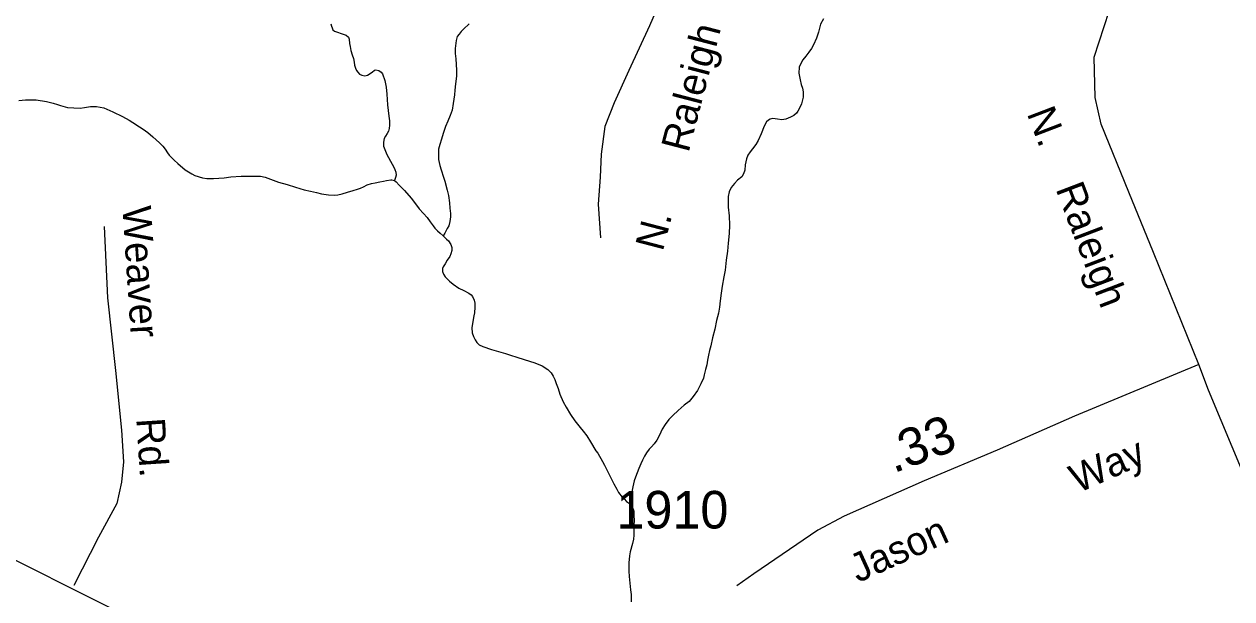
# Model space of a CAD drawing. Extents: x 2126262 to 2293712, y 749403 to 919119.
# Drawn here: x 2137114 to 2141122, y 839596 to 841505 of the extents above; entities that cross this region are included whole.
import ezdxf

# ---------------------------------------------------------------- set-up
doc = ezdxf.new("R2010")
doc.units = 0
for name, color, linetype in [('Exist Hydrographic Misc Water Feature', 7, 'Continuous'), ('Exist Road Non-System Type 51', 7, 'Continuous'), ('Exist Road Non-System Type 51 Label', 7, 'Continuous'), ('Exist Road Secondary Mileage Hundredths English Label', 7, 'Continuous'), ('Exist Road Secondary Type 51 Attributed', 7, 'Continuous'), ('Exist Road Secondary Type 51 Label', 7, 'Continuous'), ('Exist Road Secondary Type 51 Number Label', 7, 'Continuous')]:
    doc.layers.add(name, color=color, linetype=linetype)

msp = doc.modelspace()

# ---------------------------------------------------------------- linework, layer by layer
at = {"layer": 'Exist Hydrographic Misc Water Feature'}
for points in [[(2138131.8, 841506), (2138133.8, 841497.6), (2138135.9, 841492), (2138138.6, 841485.5), (2138143.9, 841481.9), (2138153.5, 841478.4), (2138166, 841474.1), (2138182, 841468), (2138189.8, 841461.5), (2138192.1, 841454.7)], [(2138591.1, 841506.3), (2138571.6, 841488.1), (2138563.8, 841480), (2138557.9, 841472), (2138551.3, 841463.6), (2138547.8, 841449.9), (2138544.4, 841423.7), (2138544.2, 841407.5), (2138546.6, 841389.2), (2138548.9, 841351.6), (2138548.9, 841331.7), (2138545.2, 841307.1), (2138543.3, 841285.9)], [(2139767.1, 841522.2), (2139756.8, 841504.7), (2139749.7, 841478.6), (2139743.7, 841458), (2139733.7, 841436), (2139727.3, 841423.9), (2139717.7, 841411.6), (2139708.2, 841398.1), (2139698, 841385.8), (2139690.6, 841371.5)], [(2138192.1, 841454.7), (2138193.9, 841440.6), (2138196.2, 841430.9), (2138198.4, 841416.8), (2138202.5, 841402.8), (2138206.4, 841390.4), (2138208.7, 841378.7), (2138210.7, 841368.3), (2138213, 841358.2), (2138216.9, 841350.7), (2138221, 841345.2), (2138227.1, 841338.2), (2138234.9, 841335), (2138245, 841333.1), (2138253, 841335.5), (2138269, 841344.8), (2138276.8, 841351.4), (2138280.9, 841352.8), (2138290.7, 841350.9), (2138298.7, 841345.2), (2138302.8, 841339.3), (2138311.2, 841317.8), (2138315.1, 841295.7), (2138317.6, 841271.8), (2138319.8, 841237.3), (2138322.1, 841217.5), (2138324.1, 841199.4), (2138326.2, 841183.6), (2138326.4, 841169.8), (2138325, 841158.2), (2138322.7, 841149.3), (2138318.8, 841141.3), (2138312.9, 841133.3), (2138308.3, 841125.1), (2138306.7, 841112.7), (2138306.7, 841099.8), (2138312.9, 841083), (2138317.4, 841071.4), (2138323.3, 841061.6), (2138329.5, 841050.1), (2138335.4, 841040.2), (2138339.7, 841031.9), (2138343.6, 841022), (2138347.1, 841012.9), (2138348.1, 841003.8), (2138345.9, 840995.6), (2138342.6, 840985.6)], [(2139690.6, 841371.5), (2139686.3, 841361.6), (2139684.9, 841341.9), (2139688.8, 841319.8), (2139692.9, 841304.2), (2139696.8, 841291.8), (2139699.2, 841280.2), (2139699.2, 841262.3), (2139693.3, 841240), (2139689.4, 841229.7), (2139681.6, 841215.8), (2139677.5, 841209.2), (2139667.8, 841201.3), (2139657.4, 841195.6), (2139642, 841189.4), (2139628.1, 841187.4), (2139613.9, 841189.2), (2139598.1, 841191.2), (2139589.9, 841188.7), (2139583.8, 841186.4), (2139577.6, 841180.9), (2139569.6, 841166.2), (2139559.6, 841141), (2139549.9, 841118.5), (2139542.3, 841104.6), (2139530.7, 841090.2), (2139522.7, 841080.4), (2139515.1, 841069.8), (2139510.8, 841057.5), (2139507.1, 841038.1), (2139505.4, 841020.1), (2139501.3, 841007.8), (2139495.4, 840998.2), (2139481.4, 840986.1), (2139471.6, 840975.8), (2139460.1, 840962.1), (2139453.6, 840948.1), (2139450.1, 840932.8), (2139450.1, 840915.3), (2139450.1, 840897.5), (2139453.8, 840868.5), (2139454.6, 840837.5), (2139453.4, 840809.4), (2139449.7, 840777.5), (2139448, 840751.3), (2139443.7, 840721.1), (2139440.2, 840687.6), (2139436.1, 840665.5), (2139430.6, 840635.1), (2139426.9, 840611.7), (2139423.2, 840585.5), (2139421.6, 840565), (2139417.9, 840545.3), (2139411.7, 840520.7), (2139406, 840491.5), (2139398.2, 840462.7), (2139392.7, 840436.8), (2139388.8, 840421.1), (2139384.7, 840405.1), (2139381.6, 840388.5), (2139378.9, 840373.1), (2139374.8, 840358.3), (2139371.1, 840340.6), (2139367.9, 840328.9), (2139359.6, 840310.3), (2139348, 840288.5), (2139334, 840268.3), (2139320.3, 840252.1), (2139304.1, 840240), (2139284.4, 840221.4), (2139266.6, 840205.5), (2139252.8, 840191.7), (2139240.7, 840175.7), (2139230.9, 840159.4), (2139227.2, 840149.8), (2139221.2, 840137.7), (2139213.2, 840123.1), (2139205.2, 840110.9), (2139195.6, 840101.4), (2139187.6, 840093.3), (2139179.6, 840081.1), (2139172.6, 840070.4), (2139165.7, 840056.8), (2139160.3, 840044.7), (2139154.2, 840029), (2139148, 840014.5), (2139142.3, 840000.7), (2139138.6, 839988.3), (2139133.7, 839968.8), (2139130, 839951.5), (2139127.1, 839934.5), (2139125.1, 839924.7), (2139123, 839912.4)], [(2137096.3, 841250.9), (2137118.2, 841252.9), (2137132.4, 841253.6), (2137153.9, 841253.1), (2137188.4, 841247.5), (2137209.9, 841242.3), (2137224, 841237.7), (2137234.1, 841234.1), (2137258.1, 841228.1), (2137278.4, 841226.6), (2137300.3, 841226.1), (2137314.3, 841228.5), (2137334.3, 841231.1), (2137354.2, 841230.9), (2137378.8, 841226.4), (2137408.2, 841213.5), (2137440.6, 841198), (2137462.7, 841186.1), (2137474.6, 841178.2), (2137496.5, 841164), (2137508.8, 841156.5), (2137524.6, 841144.7), (2137540.6, 841130.9), (2137563.2, 841110.9), (2137573.6, 841099.1), (2137581.4, 841089.5), (2137589.4, 841076.9), (2137595.4, 841069.5), (2137611.4, 841053.3), (2137623.9, 841041.6), (2137647.9, 841021.4), (2137670.2, 841007.8), (2137680.3, 841001.8), (2137706.1, 840993.9), (2137720.3, 840992.2), (2137742, 840992.5), (2137778.1, 840994.8), (2137799.8, 840997.2), (2137834.1, 840999.7), (2137866, 840999.7)], [(2138543.3, 841285.9), (2138541.5, 841269.5), (2138539.6, 841255.6), (2138537.8, 841241.7), (2138534.1, 841219.5), (2138528.2, 841201.8), (2138520.4, 841183.1), (2138512.4, 841165.2), (2138504.6, 841141.6), (2138498.8, 841122.6), (2138492.9, 841104.8), (2138489, 841089.6), (2138489.2, 841072.9), (2138489.2, 841055.1), (2138493.7, 841035.4), (2138497.6, 841021.4), (2138506, 840997), (2138509.9, 840983), (2138518.1, 840953.4), (2138522.4, 840935.3), (2138524.9, 840911.4), (2138526.9, 840893.2), (2138528.6, 840875.5), (2138529, 840865.3), (2138527.1, 840848.9), (2138523.7, 840835.2), (2138517.3, 840825.7), (2138509.9, 840811), (2138504.6, 840802)], [(2137866, 840999.7), (2137886.1, 841000.3), (2137897.8, 840999.7), (2137913.8, 840996.1), (2137940.3, 840986.1), (2137957.9, 840980.5), (2137986.4, 840972.6), (2138014.7, 840963.8), (2138043.4, 840955), (2138063.7, 840949.9), (2138083.8, 840945.3), (2138100.2, 840941.6), (2138124.2, 840937.9), (2138142.5, 840936.8), (2138154.6, 840938.2), (2138169.3, 840940.8), (2138187.4, 840947), (2138205.8, 840952.3), (2138220, 840956.3), (2138230.4, 840960.4), (2138240.1, 840965), (2138252.6, 840971.2), (2138266.1, 840975.3), (2138278.4, 840977.5), (2138294.2, 840981.1), (2138306.1, 840983.4), (2138316.1, 840985.5), (2138330.3, 840987.9), (2138334, 840987.7), (2138342.6, 840985.6)], [(2138342.6, 840985.6), (2138347.9, 840981.5), (2138358.2, 840969.9), (2138376.4, 840952.1), (2138398.6, 840926.4), (2138412.5, 840908.1), (2138424.8, 840892), (2138439.2, 840876.5), (2138450.9, 840862.9), (2138461.3, 840848.8), (2138471.4, 840834.7), (2138477.3, 840827.2), (2138485.1, 840818.7), (2138494.5, 840811.2), (2138504.6, 840802)], [(2138504.6, 840802), (2138515.9, 840791), (2138521.6, 840785.3), (2138530, 840773.5), (2138533.7, 840763.5), (2138533.3, 840753.1), (2138530.2, 840741.7), (2138526.3, 840733.4), (2138517.9, 840721.3), (2138510.7, 840709), (2138504.4, 840699.4), (2138502.5, 840692.8), (2138502.5, 840683), (2138505, 840674.9), (2138511.1, 840665.5), (2138524.9, 840651.3), (2138537.2, 840641.3), (2138556.7, 840627.8), (2138573.3, 840620), (2138589.3, 840611.5), (2138597.7, 840605.8), (2138601.4, 840599.9), (2138607.3, 840588), (2138609.6, 840578.4), (2138609.4, 840564.6), (2138608.1, 840546.2), (2138605.9, 840535.9), (2138604, 840524.5), (2138600.1, 840495.8), (2138600.5, 840480), (2138604.9, 840467.9), (2138610.6, 840456.2), (2138616.3, 840447.9), (2138624.3, 840440.2), (2138635.8, 840434.5), (2138664.3, 840424.1), (2138710.9, 840410.5), (2138727.9, 840405.5), (2138748.8, 840399.1), (2138773.2, 840391.4), (2138790.8, 840385.8), (2138809.1, 840379.8), (2138832.9, 840370.5), (2138851.9, 840357.5), (2138862.6, 840346.6), (2138869.8, 840336.1), (2138875.3, 840324.4), (2138879.6, 840311.9), (2138885.8, 840294.8), (2138892.1, 840276.4), (2138902.2, 840250.9), (2138912.4, 840232.7), (2138926.6, 840208.2), (2138940.9, 840187), (2138959, 840165.2), (2138969, 840153.5), (2138981.1, 840137.5), (2138993.6, 840117.8), (2139011.5, 840087.9), (2139017.8, 840079.6), (2139033.6, 840052.1), (2139040, 840039.7), (2139062.5, 839995.8), (2139070.7, 839978.3), (2139080.8, 839960.1), (2139086.7, 839949.9), (2139099, 839934.2), (2139104.8, 839928.5), (2139113.2, 839919.9), (2139123, 839912.4)], [(2139123, 839912.4), (2139133.1, 839899.1), (2139137.2, 839887.5), (2139137.2, 839872.9), (2139138, 839856.6), (2139137.6, 839842.4), (2139137.6, 839834.3), (2139137.6, 839824.5), (2139137.4, 839807.9), (2139136.6, 839794.7), (2139132.5, 839780.3), (2139124.9, 839752.6), (2139122.6, 839738.8), (2139121, 839716.3), (2139121, 839688.7), (2139121.4, 839670.4), (2139123.6, 839648.1), (2139125.9, 839626.3), (2139127.9, 839610.6), (2139128.1, 839586.6)]]:
    msp.add_lwpolyline(points, dxfattribs=at)
at = {"layer": 'Exist Road Non-System Type 51'}
msp.add_lwpolyline([(2137379.8, 840832.9), (2137390.8, 840595.8), (2137417.1, 840354.3), (2137436.9, 840156.8), (2137443.5, 840051.4), (2137436.9, 839983.3), (2137421.5, 839913.1), (2137360.1, 839801.1), (2137278.4, 839640.5)], dxfattribs=at)
at = {"layer": 'Exist Road Secondary Type 51 Attributed'}
for points in [[(2139269.1, 841683.8), (2139189.3, 841499.4), (2139120.2, 841350.9), (2139072, 841243.9), (2139040.4, 841164.5), (2139028.5, 841072.8), (2139024.9, 840996.8), (2139019, 840907), (2139026.7, 840794.8)], [(2141011.8, 840374.9), (2140861.7, 840747), (2140779.8, 840946.6), (2140688.5, 841172.5), (2140668.3, 841260.9), (2140665.1, 841395), (2140714.2, 841548)], [(2141011.8, 840374.9), (2140600.1, 840202.7), (2140342.4, 840090.2), (2140100.2, 839988.6), (2139835.3, 839870.5), (2139748.1, 839824.2), (2139535.7, 839679.6), (2139479.4, 839639.9)], [(2141165.2, 840000.8), (2141044.2, 840289.2), (2141011.8, 840374.9)], [(2136268.5, 840081.4), (2136362.6, 840057.4), (2136501.7, 840007.2), (2136664, 839926), (2136940.2, 839797.1), (2137462.7, 839535.1), (2137674.5, 839428.7), (2137977.4, 839180.4), (2138132.6, 839043.2), (2138330.6, 838849.2), (2138544.5, 838652.7), (2138838.4, 838356.7), (2139013, 838191.1), (2139320.7, 837893.9), (2139707, 837516.6), (2139826.8, 837400.7), (2139907.5, 837304.7), (2140358, 836679.5), (2140503.4, 836472.4), (2140610.7, 836338.1), (2140708.5, 836234.1), (2140798.2, 836151.3), (2140885.4, 836100.6), (2140973.7, 836060.8)]]:
    msp.add_lwpolyline(points, dxfattribs=at)

# ---------------------------------------------------------------- texts
at = {"layer": 'Exist Road Non-System Type 51 Label'}
for s, p in [('Weaver', (2137439.8, 840898.1)), ('Rd.', (2137485.8, 840194.5))]:
    msp.add_text(s, height=95, rotation=273.7402, dxfattribs=at).set_placement(p)
at = {"layer": 'Exist Road Secondary Mileage Hundredths English Label'}
msp.add_text('.33', height=125, rotation=20.5479, dxfattribs=at).set_placement((2139999.2, 840012.8))
at = {"layer": 'Exist Road Secondary Type 51 Label'}
for s, rotation, p in [('N.      Raleigh', 75.3726, (2139232.9, 840747.4)), ('N.    Raleigh', 290.892, (2140440.4, 841208.6)), ('Way', 24.0034, (2140610.7, 839946.1)), ('Jason', 24.4069, (2139880.8, 839648.4))]:
    msp.add_text(s, height=95, rotation=rotation, dxfattribs=at).set_placement(p)
at = {"layer": 'Exist Road Secondary Type 51 Number Label'}
msp.add_text('1910', height=125, dxfattribs=at).set_placement((2139079.2, 839829.8))

doc.saveas('drawing.dxf')
